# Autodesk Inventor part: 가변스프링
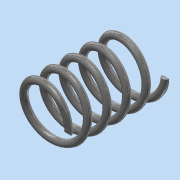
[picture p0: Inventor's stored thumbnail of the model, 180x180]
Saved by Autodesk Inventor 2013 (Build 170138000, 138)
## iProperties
Created: 2018-10
Part Number: 가변스프링
Material: 스테인리스강
Document SubType Name: Modeling
Designer: Administrator
Density: 8.08 g/cm^3
Mass: 6.28631 g
Surface Area: 15.7884 cm^2
Volume: 0.778008 cm^3
Author: Administrator
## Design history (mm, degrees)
sketch "스케치1"
  geometry: L1 (0, 0)-(0, 29.235); L2 (0, 0)-(8, 0); L3 (0, 29.235)-(8, 29.235); C1 r 1 at (8, 0)
  constraints: 6 end point, 1 centre point, 1 horizontal alignment, 1 parallel, 1 perpendicular, 1 vertical
  dimensions: "d0" = 29.23502 distance of L1.start L1.end (derived); "d1" = 2 diameter of C1; "d2" = 16 diameter of L2.end L1; "d3" = 8 distance of L1.end L3.end
feature "코일1" sketch "스케치1" pitch "d4" = 10; turns "d6" = 5; dims "d5" = 29.23502 (= d0), "d7" = 0, angle "d8" = 90 deg, angle "d9" = 90 deg, "d10" = 0, "d11" = 0
sketch "스케치2"
  geometry: L1 (29.235, 10)-(0, 10); L2 (0, 10)-(0, -10); L3 (0, -10)-(29.235, -10); L4 (29.235, -10)-(29.235, 10); 2 further points
  constraints: 8 end point, 2 parallel, 1 coincident, 1 horizontal, 1 midpoint, 1 perpendicular
  dimensions: "d12" = 20 distance of L1.end L2.end; "d14" = 29.23502 distance of L2.end L3.end (derived)
extrude "돌출1" sketch "스케치2" stored distance "d15" = 0; taper "d16" = 0 deg
node "솔리드1"
